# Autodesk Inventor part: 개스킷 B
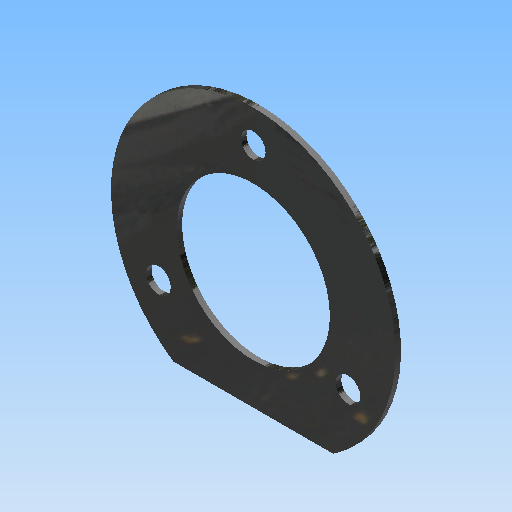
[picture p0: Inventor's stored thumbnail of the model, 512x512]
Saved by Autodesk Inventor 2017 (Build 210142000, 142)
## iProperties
Created: 2020-04
Part Number: 개스킷 B
Material: 고무
Document SubType Name: Modeling
Designer: mduedu
Density: 0.93 g/cm^3
Mass: 1.27493 g
Surface Area: 30.3371 cm^2
Volume: 1.37089 cm^3
Appearance: 고무 - 검은색 - 버전 1.1
Author: mduedu
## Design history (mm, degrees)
sketch "스케치1"
  geometry: C1 r 26 at (0, 0); 1 further point
  constraints: 1 centre point, 1 coincident
  dimensions: "d0" = 52 diameter of C1
extrude "돌출1" new body sketch "스케치1" distance "d1" = 1; taper "d2" = 0 deg
sketch "스케치2"
  geometry: L1 (-14.62, -21.5)-(14.62, -21.5); A1 r 26 centre (0, 0) between (-14.62, -21.5) and (14.62, -21.5) reference; 1 further point
  constraints: 2 end point, 2 point on circle, 1 horizontal
  dimensions: "d3" = 21.5 distance from line of L1 point (0, 0)
extrude "돌출2" cut sketch "스케치2" stored distance "d4" = 1; taper "d5" = 0 deg
sketch "스케치3" dims "d6" = 40
  geometry: 3 further points
  constraints: 2 vertical alignment, 1 coincident, 2 other
hole "구멍1" sketch "스케치3" at (0, 20) diameter "d7" = 4.5; stored, may be unused: countersink angle "d11" = 90 deg, drill point angle "d13" = 118 deg; dims "d8" = 6, "d9" = 4, "d10" = 2, "d12" = 8
sketch "스케치4"
  geometry: C1 r 14 at (0, 0); 1 further point
  constraints: 1 centre point, 1 coincident
  dimensions: "d17" = 28 diameter of C1
extrude "돌출3" cut sketch "스케치4" stored distance "d18" = 1; taper "d19" = 0 deg
node "솔리드1"
pattern_circular "원형 패턴1" dims angle "d15" = 360 deg
node "투영된 루프1"
